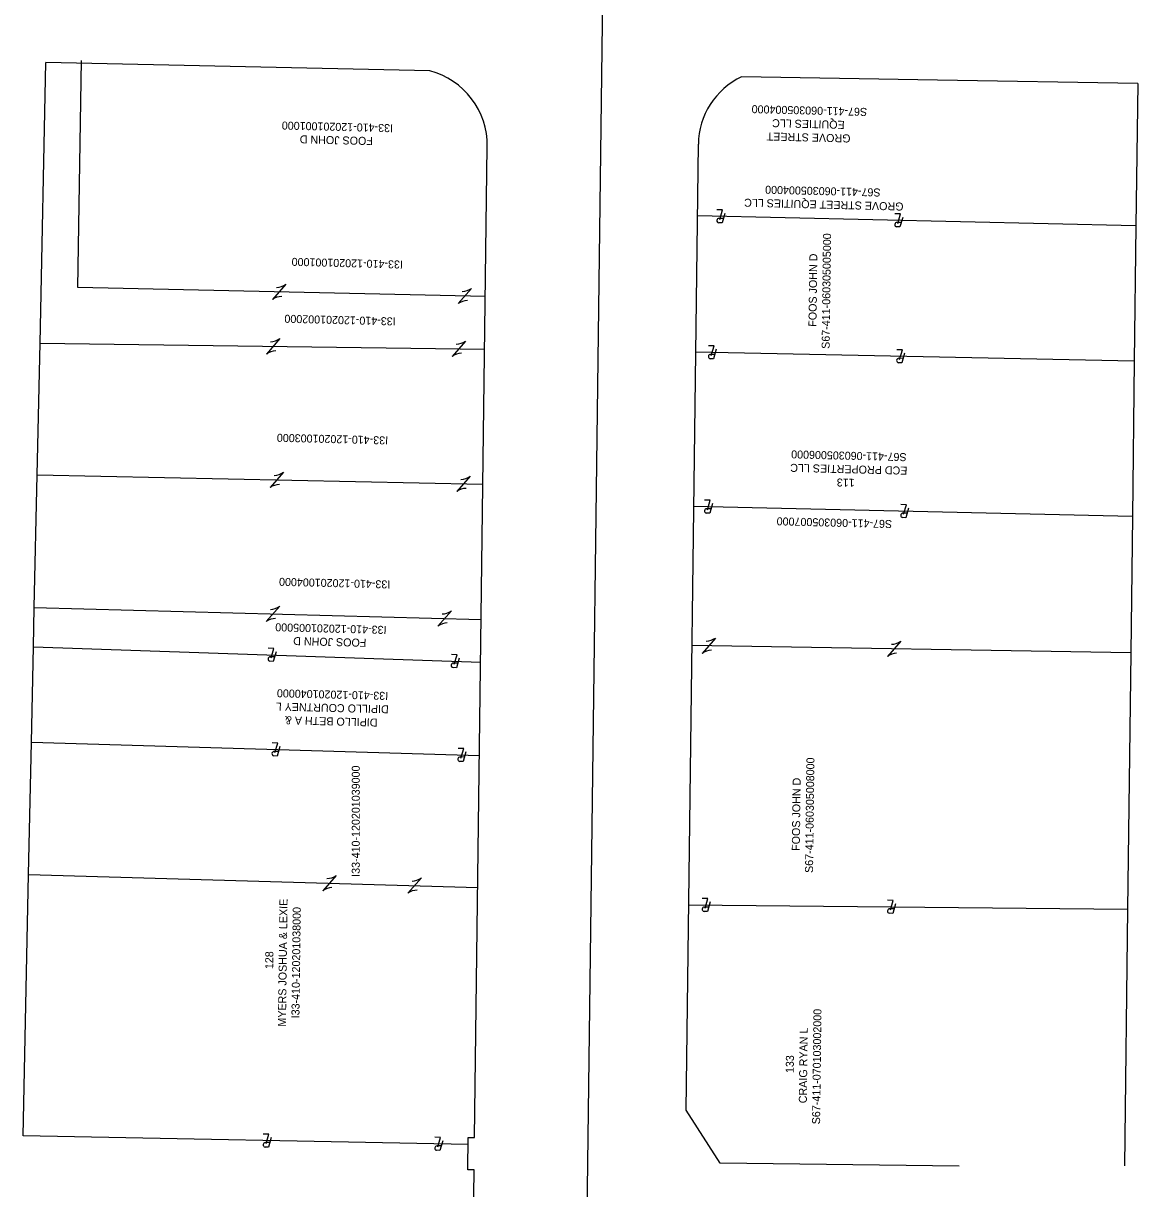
# Model space of a CAD drawing. Extents: x 1652206 to 1653153, y 604222 to 614600.
# Drawn here: x 1652372.3 to 1652715.5, y 606498.1 to 606857 of the extents above; entities that cross this region are included whole.
import ezdxf

# ---------------------------------------------------------------- set-up
doc = ezdxf.new("R2010")
doc.units = 0
for name, color, linetype in [('_CIVIL_CONSTRUCTION', 7, 'Continuous'), ('GE_P_Alignment_100_Bearings', 7, 'Continuous'), ('GE_P_Alignment_100_Cardinal_Points', 7, 'Continuous'), ('GE_P_Alignment_100_Distances', 7, 'Continuous')]:
    doc.layers.add(name, color=color, linetype=linetype)

msp = doc.modelspace()

# ---------------------------------------------------------------- linework, layer by layer
at = {"layer": '_CIVIL_CONSTRUCTION'}
msp.add_line((1652516.96, 604222.43), (1652550.86, 606872.07), dxfattribs=at)
at = {"layer": 'GE_P_Alignment_100_Bearings'}
for p, q in [((1652377.4, 606758.47), (1652379.2, 606844.9)), ((1652389.02, 606775.65), (1652390.21, 606845.49)), ((1652715.51, 606838.45), (1652714.97, 606794.65)), ((1652714.97, 606794.65), (1652579.91, 606797.68)), ((1652587.89, 606796.88), (1652586.59, 606796.91)), ((1652587.1, 606797.52), (1652587.1, 606797.52)), ((1652641.88, 606796.29), (1652641.88, 606796.29)), ((1652642.67, 606795.65), (1652641.38, 606795.68)), ((1652714.97, 606794.65), (1652714.46, 606752.93)), ((1652514.59, 606772.87), (1652389.02, 606775.65)), ((1652453.12, 606776.63), (1652449.02, 606771.92)), ((1652510.3, 606775.37), (1652506.19, 606770.66)), ((1652451.07, 606774.28), (1652451.07, 606774.28)), ((1652508.25, 606773.01), (1652508.25, 606773.01)), ((1652376.52, 606717.91), (1652377.4, 606758.47)), ((1652377.4, 606758.47), (1652514.38, 606756.67)), ((1652451.23, 606759.9), (1652447.17, 606755.15)), ((1652449.2, 606757.53), (1652449.2, 606757.53)), ((1652508.43, 606759.15), (1652504.37, 606754.4)), ((1652506.4, 606756.78), (1652506.4, 606756.78)), ((1652714.46, 606752.93), (1652579.37, 606755.77)), ((1652585.26, 606755.02), (1652583.96, 606755.05)), ((1652584.47, 606755.66), (1652584.47, 606755.66)), ((1652643.25, 606753.8), (1652641.95, 606753.83)), ((1652642.46, 606754.44), (1652642.46, 606754.44)), ((1652714.46, 606752.93), (1652713.88, 606705.15)), ((1652375.64, 606677.09), (1652376.52, 606717.91)), ((1652376.52, 606717.91), (1652513.85, 606715.05)), ((1652452.39, 606718.73), (1652448.29, 606714.01)), ((1652509.89, 606717.53), (1652505.79, 606712.82)), ((1652450.34, 606716.37), (1652450.34, 606716.37)), ((1652507.84, 606715.17), (1652507.84, 606715.17)), ((1652713.88, 606705.15), (1652578.76, 606708.24)), ((1652584.06, 606707.5), (1652582.77, 606707.53)), ((1652583.27, 606708.14), (1652583.27, 606708.14)), ((1652644.5, 606706.12), (1652643.2, 606706.14)), ((1652643.71, 606706.76), (1652643.71, 606706.76)), ((1652713.88, 606705.15), (1652713.37, 606663.16)), ((1652451.24, 606677.48), (1652447.11, 606672.78)), ((1652375.4, 606665.03), (1652375.64, 606677.09)), ((1652375.64, 606677.09), (1652513.31, 606673.42)), ((1652449.17, 606675.13), (1652449.17, 606675.13)), ((1652504.11, 606676.07), (1652499.98, 606671.38)), ((1652502.05, 606673.72), (1652502.05, 606673.72)), ((1652585.44, 606667.7), (1652581.36, 606662.96)), ((1652642.51, 606666.74), (1652638.43, 606662.01)), ((1652374.76, 606635.59), (1652375.4, 606665.03)), ((1652375.4, 606665.03), (1652513.15, 606660.3)), ((1652713.37, 606663.16), (1652578.22, 606665.42)), ((1652583.4, 606665.33), (1652583.4, 606665.33)), ((1652640.47, 606664.37), (1652640.47, 606664.37)), ((1652713.37, 606663.16), (1652712.4, 606584.21)), ((1652449.64, 606661.86), (1652448.35, 606661.9)), ((1652448.86, 606662.51), (1652448.86, 606662.51)), ((1652506.05, 606659.92), (1652504.75, 606659.97)), ((1652505.27, 606660.57), (1652505.27, 606660.57)), ((1652373.9, 606594.91), (1652374.76, 606635.59)), ((1652374.76, 606635.59), (1652512.78, 606631.54)), ((1652450.84, 606632.73), (1652449.54, 606632.77)), ((1652450.06, 606633.38), (1652450.06, 606633.38)), ((1652508.13, 606631.05), (1652506.83, 606631.09)), ((1652507.34, 606631.7), (1652507.34, 606631.7)), ((1652372.26, 606514.41), (1652373.9, 606594.91)), ((1652373.9, 606594.91), (1652512.26, 606590.92)), ((1652468.63, 606594.58), (1652464.49, 606589.89)), ((1652466.56, 606592.23), (1652466.56, 606592.23)), ((1652494.86, 606593.82), (1652490.73, 606589.14)), ((1652492.79, 606591.48), (1652492.79, 606591.48)), ((1652577.19, 606585.54), (1652712.4, 606584.21)), ((1652583.36, 606584.85), (1652582.06, 606584.87)), ((1652582.56, 606585.48), (1652582.56, 606585.48)), ((1652640.43, 606584.29), (1652639.13, 606584.3)), ((1652639.63, 606584.92), (1652639.63, 606584.92)), ((1652712.4, 606584.21), (1652711.44, 606505.17)), ((1652509.25, 606511.76), (1652372.26, 606514.41)), ((1652447.36, 606512.95), (1652447.36, 606512.95)), ((1652448.15, 606512.31), (1652446.85, 606512.34)), ((1652500.99, 606511.29), (1652499.7, 606511.32)), ((1652500.2, 606511.93), (1652500.2, 606511.93))]:
    msp.add_line(p, q, dxfattribs=at)
for points in [[(1652586.81, 606796.57), (1652587.67, 606799.5), (1652585.92, 606799.54)], [(1652588.34, 606798.46), (1652587.49, 606795.51), (1652586.46, 606795.54)], [(1652641.6, 606795.34), (1652642.45, 606798.27), (1652640.71, 606798.31)], [(1652643.13, 606797.23), (1652642.28, 606794.28), (1652641.25, 606794.31)], [(1652584.18, 606754.7), (1652585.04, 606757.64), (1652583.29, 606757.68)], [(1652585.71, 606756.6), (1652584.87, 606753.65), (1652583.83, 606753.68)], [(1652642.18, 606753.49), (1652643.03, 606756.43), (1652641.28, 606756.46)], [(1652643.7, 606755.38), (1652642.86, 606752.43), (1652641.83, 606752.46)], [(1652582.99, 606707.18), (1652583.84, 606710.12), (1652582.1, 606710.16)], [(1652584.52, 606709.08), (1652583.67, 606706.13), (1652582.64, 606706.16)], [(1652643.42, 606705.8), (1652644.28, 606708.74), (1652642.54, 606708.78)], [(1652644.96, 606707.7), (1652644.11, 606704.75), (1652643.07, 606704.78)], [(1652448.56, 606661.56), (1652449.46, 606664.49), (1652447.71, 606664.54)], [(1652450.12, 606663.43), (1652449.23, 606660.5), (1652448.2, 606660.53)], [(1652504.97, 606659.62), (1652505.86, 606662.55), (1652504.12, 606662.61)], [(1652506.52, 606661.5), (1652505.64, 606658.56), (1652504.61, 606658.6)], [(1652449.76, 606632.43), (1652450.64, 606635.36), (1652448.89, 606635.41)], [(1652451.31, 606634.31), (1652450.44, 606631.37), (1652449.41, 606631.4)], [(1652507.05, 606630.75), (1652507.93, 606633.68), (1652506.18, 606633.73)], [(1652508.59, 606632.63), (1652507.72, 606629.69), (1652506.69, 606629.72)], [(1652582.29, 606584.53), (1652583.11, 606587.48), (1652581.36, 606587.49)], [(1652583.79, 606586.44), (1652582.98, 606583.48), (1652581.95, 606583.49)], [(1652639.36, 606583.97), (1652640.18, 606586.91), (1652638.43, 606586.93)], [(1652640.86, 606585.88), (1652640.05, 606582.92), (1652639.02, 606582.93)], [(1652447.07, 606512), (1652447.92, 606514.94), (1652446.18, 606514.97)], [(1652448.6, 606513.9), (1652447.76, 606510.95), (1652446.73, 606510.97)], [(1652499.92, 606510.98), (1652500.77, 606513.92), (1652499.02, 606513.95)], [(1652501.44, 606512.88), (1652500.6, 606509.93), (1652499.57, 606509.95)]]:
    msp.add_lwpolyline(points, dxfattribs=at)
for centre, radius, start, end in [((1652586.58, 606796.22), 0.69, 89.1864, 260.0435), ((1652641.37, 606794.99), 0.69, 89.1864, 260.0435), ((1652450.05, 606781), 5.34, 272.429, 305.0716), ((1652507.23, 606779.74), 5.34, 272.429, 305.0716), ((1652452.08, 606767.55), 5.34, 92.429, 125.0716), ((1652509.26, 606766.29), 5.34, 92.429, 125.0716), ((1652448.13, 606764.24), 5.34, 272.9438, 305.5863), ((1652505.33, 606763.49), 5.34, 272.9438, 305.5863), ((1652450.28, 606750.81), 5.34, 92.9438, 125.5863), ((1652507.47, 606750.06), 5.34, 92.9438, 125.5863), ((1652583.95, 606754.36), 0.69, 89.2674, 260.1245), ((1652641.95, 606753.14), 0.69, 89.2674, 260.1245), ((1652449.31, 606723.09), 5.34, 272.502, 305.1446), ((1652506.81, 606721.89), 5.34, 272.502, 305.1446), ((1652451.36, 606709.65), 5.34, 92.502, 125.1446), ((1652508.86, 606708.45), 5.34, 92.502, 125.1446), ((1652582.76, 606706.84), 0.69, 89.1624, 260.0196), ((1652643.19, 606705.46), 0.69, 89.1624, 260.0196), ((1652448.19, 606681.86), 5.34, 272.1707, 304.8133), ((1652501.06, 606680.45), 5.34, 272.1707, 304.8133), ((1652450.16, 606668.4), 5.34, 92.1707, 124.8133), ((1652503.03, 606667), 5.34, 92.1707, 124.8133), ((1652582.35, 606672.05), 5.34, 272.736, 305.3786), ((1652639.42, 606671.09), 5.34, 272.736, 305.3786), ((1652584.45, 606658.61), 5.34, 92.736, 125.3786), ((1652448.33, 606661.21), 0.69, 88.5071, 259.3642), ((1652504.74, 606659.28), 0.69, 88.5071, 259.3642), ((1652641.52, 606657.66), 5.34, 92.736, 125.3786), ((1652449.53, 606632.08), 0.69, 88.792, 259.6491), ((1652506.81, 606630.4), 0.69, 88.792, 259.6491), ((1652465.59, 606598.96), 5.34, 272.0429, 304.6854), ((1652491.82, 606598.21), 5.34, 272.0429, 304.6854), ((1652467.53, 606585.51), 5.34, 92.0429, 124.6854), ((1652493.76, 606584.75), 5.34, 92.0429, 124.6854), ((1652582.06, 606584.18), 0.69, 89.908, 260.7651), ((1652639.13, 606583.62), 0.69, 89.908, 260.7651), ((1652446.84, 606511.65), 0.69, 89.3621, 260.2193), ((1652499.69, 606510.63), 0.69, 89.3621, 260.2193)]:
    msp.add_arc(centre, radius, start, end, dxfattribs=at)
at = {"layer": 'GE_P_Alignment_100_Distances'}
for p, q in [((1652497.48, 606842.38), (1652379.2, 606844.9)), ((1652653.86, 606839.5), (1652593.46, 606840.52)), ((1652715.51, 606838.45), (1652653.86, 606839.5)), ((1652576.39, 606522.27), (1652580.19, 606819.74)), ((1652586.95, 606505.97), (1652576.39, 606522.27)), ((1652660.54, 606505.03), (1652586.95, 606505.97))]:
    msp.add_line(p, q, dxfattribs=at)
msp.add_lwpolyline([(1652507.27, 606201.32), (1652511.14, 606503.89), (1652509.15, 606503.92), (1652509.27, 606513.92), (1652511.27, 606513.89), (1652515.18, 606819.04)], dxfattribs=at)
for centre, radius, start, end in [((1652491.34, 606819.34), 23.84, 359.267, 75.0863), ((1652603.56, 606819.44), 23.37, 115.6166, 179.267)]:
    msp.add_arc(centre, radius, start, end, dxfattribs=at)

# ---------------------------------------------------------------- texts
at = {"layer": 'GE_P_Alignment_100_Cardinal_Points'}
for s, height, rotation, p in [('S67-411-060305004000', 2.4653, 178.565, (1652632.19, 606830.91)), ('I33-410-120201001000', 2.4653, 178.565, (1652486.18, 606825.9)), ('EQUITIES LLC', 2.4653, 178.565, (1652625.28, 606826.93)), ('FOOS JOHN D', 2.4653, 178.565, (1652479.96, 606821.94)), ('GROVE STREET ', 2.4653, 178.565, (1652627.07, 606822.74)), ('S67-411-060305004000', 2.4653, 178.565, (1652636.34, 606806.1)), ('GROVE STREET EQUITIES LLC', 2.4653, 178.565, (1652643.4, 606801.77)), ('S67-411-060305005000', 2.4653, 89.2843, (1652620.62, 606756.74)), ('FOOS JOHN D', 2.4653, 89.2843, (1652616.56, 606763.54)), ('I33-410-120201001000', 2.4653, 178.565, (1652489.21, 606783.92)), ('I33-410-120201002000', 2.4653, 178.565, (1652486.99, 606766.4)), ('I33-410-120201003000', 2.4653, 178.565, (1652484.66, 606729.75)), ('S67-411-060305006000', 2.4653, 178.565, (1652644.36, 606724.61)), ('ECD PROPERTIES LLC', 2.4653, 178.565, (1652644.6, 606720.45)), ('113', 2.465, 178.565, (1652628.36, 606716.7)), ('S67-411-060305007000', 2.4653, 178.565, (1652639.89, 606704)), ('I33-410-120201004000', 2.4653, 178.565, (1652485.33, 606685.4)), ('I33-410-120201005000', 2.4653, 178.565, (1652484.17, 606671.4)), ('FOOS JOHN D', 2.4653, 178.565, (1652477.95, 606667.44)), ('I33-410-120201040000', 2.4653, 178.565, (1652484.68, 606651.08)), ('DIPILLO COURTNEY L', 2.4653, 178.565, (1652484.84, 606646.96)), ('DIPILLO BETH A &', 2.4653, 178.565, (1652481.38, 606642.89)), ('S67-411-060305008000', 2.4653, 89.2843, (1652615.5, 606595.34)), ('I33-410-120201039000', 2.4653, 90, (1652475.89, 606594.16)), ('FOOS JOHN D', 2.4653, 89.2843, (1652611.43, 606602.14)), ('MYERS JOSHUA & LEXIE', 2.4653, 89.2843, (1652453.15, 606548.02)), ('I33-410-120201038000', 2.4653, 89.2843, (1652457.3, 606550.58)), ('128', 2.465, 89.2843, (1652449.21, 606565.72)), ('S67-411-070103002000', 2.4653, 89.2843, (1652617.67, 606517.94)), ('CRAIG RYAN L', 2.4653, 89.2843, (1652613.59, 606524.43)), ('133', 2.465, 89.2843, (1652609.56, 606533.72))]:
    msp.add_text(s, height=height, rotation=rotation, dxfattribs=at).set_placement(p)

doc.saveas('drawing.dxf')
